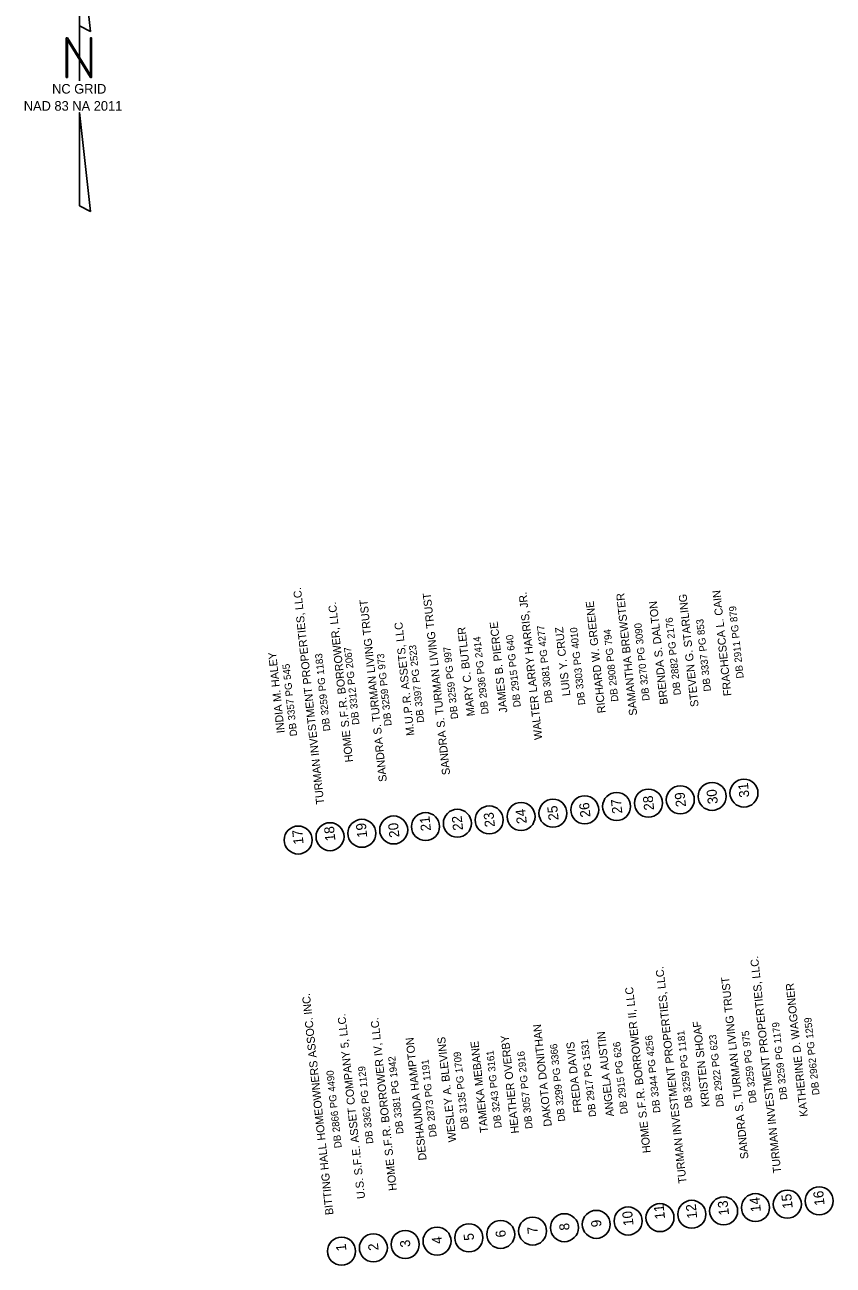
# Model space of a CAD drawing. Extents: x 1614427 to 1617186, y 896524 to 905462.
# Drawn here: x 1615655 to 1616160, y 902076 to 902852 of the extents above; entities that cross this region are included whole.
import ezdxf

# ---------------------------------------------------------------- set-up
doc = ezdxf.new("R2010")
doc.units = 0
for name, color, linetype in [('CTL North Arrow NAD 83 NA 2011 CELL', 7, 'Continuous'), ('Exist Property Deed Book Text', 7, 'Continuous'), ('Exist Property Owner Number CELL', 7, 'Continuous'), ('Exist Property Owner Text', 7, 'Continuous')]:
    doc.layers.add(name, color=color, linetype=linetype)

msp = doc.modelspace()

# ---------------------------------------------------------------- linework, layer by layer
at = {"layer": 'CTL North Arrow NAD 83 NA 2011 CELL'}
msp.add_line((1615689.76, 902821.93), (1615689.76, 902821.93), dxfattribs=at)
for points in [[(1615689.61, 902909.22), (1615689.61, 902850.9), (1615696.48, 902847.46)], [(1615681.38, 902818.67), (1615682.07, 902818.67), (1615682.07, 902842), (1615696.48, 902818.67), (1615697.17, 902818.67), (1615697.17, 902843.36), (1615696.48, 902843.36), (1615696.48, 902820.03), (1615682.07, 902843.36), (1615681.38, 902843.36)], [(1615689.61, 902738.38), (1615696.48, 902734.97), (1615689.61, 902796.71)]]:
    msp.add_lwpolyline(points, close=True, dxfattribs=at)
msp.add_lwpolyline([(1615689.61, 902850.9), (1615689.61, 902816.6)], dxfattribs=at)
at = {"layer": 'Exist Property Owner Number CELL'}
for centre in [(1616064.92, 902367.33), (1616084.81, 902369.42), (1616104.7, 902371.52), (1615985.36, 902358.94), (1616005.25, 902361.04), (1616025.14, 902363.14), (1616045.03, 902365.23), (1615905.8, 902350.56), (1615925.69, 902352.65), (1615945.58, 902354.75), (1615965.47, 902356.85), (1615826.24, 902342.17), (1615846.13, 902344.27), (1615866.02, 902346.36), (1615885.91, 902348.46), (1616092, 902110.4), (1616111.89, 902112.5), (1616131.78, 902114.59), (1616151.67, 902116.69), (1616012.44, 902102.02), (1616032.33, 902104.11), (1616052.22, 902106.21), (1616072.11, 902108.31), (1615952.77, 902095.73), (1615972.66, 902097.82), (1615992.55, 902099.92), (1615873.21, 902087.34), (1615893.1, 902089.44), (1615912.99, 902091.53), (1615932.88, 902093.63), (1615853.32, 902085.25)]:
    msp.add_circle(centre, 8.75, dxfattribs=at)

# ---------------------------------------------------------------- texts
at = {"layer": 'CTL North Arrow NAD 83 NA 2011 CELL'}
for s, p in [('NC GRID', (1615672.53, 902808.6)), ('NAD 83 NA 2011', (1615654.84, 902797.92))]:
    msp.add_text(s, height=6, dxfattribs=at).set_placement(p)
at = {"layer": 'Exist Property Deed Book Text'}
for s, p in [('DB 2911 PG 879', (1616104.55, 902443.39)), ('DB 3081 PG 4277', (1615985.05, 902427.99)), ('DB 3303 PG 4010', (1616005.62, 902426.73)), ('DB 3270 PG 3090', (1616045.8, 902429.41)), ('DB 2882 PG 2176', (1616065.33, 902432.91)), ('DB 3337 PG 853', (1616084.1, 902435.27)), ('DB 2936 PG 2414', (1615945.23, 902421)), ('DB 2915 PG 640', (1615965.29, 902425.42)), ('DB 2908 PG 794', (1616026.29, 902428.87)), ('DB 3312 PG 2067', (1615864.53, 902414.37)), ('DB 3397 PG 2523', (1615905.01, 902415.72)), ('DB 3259 PG 997', (1615926.19, 902417.97)), ('DB 3357 PG 545', (1615825.65, 902407.26)), ('DB 3259 PG 1183', (1615846.36, 902410.41)), ('DB 3259 PG 973', (1615884.67, 902413.68)), ('DB 3259 PG 1179', (1616131.83, 902180.05)), ('DB 2962 PG 1259', (1616151.93, 902183.01)), ('DB 3344 PG 4256', (1616052.55, 902171.86)), ('DB 3259 PG 1181', (1616072.57, 902174.83)), ('DB 2922 PG 623', (1616092.11, 902175.6)), ('DB 3259 PG 975', (1616112.57, 902177.99)), ('DB 3299 PG 3366', (1615993.11, 902166.5)), ('DB 2917 PG 1531', (1616012.42, 902169.39)), ('DB 2915 PG 626', (1616032.13, 902171.11)), ('DB 3381 PG 1942', (1615892.07, 902158.72)), ('DB 2873 PG 1191', (1615912.78, 902156.75)), ('DB 3135 PG 1709', (1615932.85, 902161.57)), ('DB 3243 PG 3161', (1615953.37, 902162.37)), ('DB 3057 PG 2916', (1615972.69, 902161.91)), ('DB 2866 PG 4490', (1615853.46, 902149.88)), ('DB 3362 PG 1129', (1615873.25, 902152.56))]:
    msp.add_text(s, height=4.5, rotation=96.11804, dxfattribs=at).set_placement(p)
at = {"layer": 'Exist Property Owner Number CELL'}
for s, p in [('31', (1616108.11, 902369.06)), ('27', (1616028.74, 902358.92)), ('28', (1616048.63, 902361.01)), ('29', (1616068.52, 902363.11)), ('30', (1616088.43, 902364.96)), ('23', (1615949.18, 902350.53)), ('24', (1615969.07, 902352.63)), ('25', (1615988.96, 902354.73)), ('26', (1616008.86, 902356.67)), ('19', (1615869.43, 902343.91)), ('20', (1615889.53, 902344)), ('21', (1615909.21, 902348.1)), ('22', (1615929.29, 902348.44)), ('17', (1615829.65, 902339.72)), ('18', (1615849.54, 902341.81)), ('14', (1616115.3, 902110.04)), ('15', (1616135.19, 902112.14)), ('16', (1616155.09, 902114.09)), ('11', (1616055.44, 902105.51)), ('12', (1616075.52, 902105.85)), ('13', (1616095.41, 902107.95)), ('9', (1616015.74, 902100.59)), ('10', (1616035.76, 902101.41)), ('5', (1615936.18, 902092.2)), ('6', (1615956.08, 902094.15)), ('7', (1615975.96, 902096.4)), ('8', (1615995.85, 902098.49)), ('1', (1615856.43, 902085.58)), ('2', (1615876.51, 902085.91)), ('3', (1615896.4, 902088.01)), ('4', (1615916.29, 902090.11))]:
    msp.add_text(s, height=6.25, rotation=96.11804, dxfattribs=at).set_placement(p)
at = {"layer": 'Exist Property Owner Text'}
for s, p in [('TURMAN INVESTMENT PROPERTIES, LLC.', (1615842.51, 902364.69)), ('HOME S.F.R. BORROWER, LLC.', (1615860.56, 902391.05)), ('SANDRA S. TURMAN LIVING TRUST', (1615881.66, 902378.81)), ('SANDRA S. TURMAN LIVING TRUST', (1615921.18, 902383.08)), ('WALTER LARRY HARRIS, JR.', (1615978.76, 902405.08)), ('RICHARD W. GREENE', (1616018.31, 902421.69)), ('SAMANTHA BREWSTER', (1616038.03, 902420.25)), ('BRENDA S. DALTON', (1616057.2, 902427.09)), ('STEVEN G. STARLING', (1616076.38, 902425.62)), ('FRACHESCA L. CAIN', (1616096.98, 902432.41)), ('M.U.P.R. ASSETS, LLC', (1615898.87, 902407.63)), ('MARY C. BUTLER', (1615936.61, 902419.78)), ('JAMES B. PIERCE', (1615956.91, 902421.97)), ('LUIS Y. CRUZ', (1615996.26, 902432.41)), ('INDIA M. HALEY', (1615817.86, 902409.22)), ('TURMAN INVESTMENT PROPERTIES, LLC.', (1616127.98, 902134.33)), ('TURMAN INVESTMENT PROPERTIES, LLC.', (1616068.85, 902127.84)), ('HOME S.F.R. BORROWER II, LLC', (1616046.48, 902146.83)), ('SANDRA S. TURMAN LIVING TRUST', (1616107.56, 902143.09)), ('KATHERINE D. WAGONER', (1616144.63, 902169.55)), ('BITTING HALL HOMEOWNERS ASSOC. INC.', (1615848.34, 902108.13)), ('U.S. S.F.E. ASSET COMPANY 5, LLC.', (1615868.08, 902118.2)), ('HOME S.F.R. BORROWER IV, LLC.', (1615887.9, 902123.29)), ('KRISTEN SHOAF', (1616083.34, 902175.72)), ('HEATHER OVERBY', (1615964.24, 902159.08)), ('DAKOTA DONITHAN', (1615984.69, 902163.42)), ('ANGELA AUSTIN', (1616023.54, 902169.64)), ('DESHAUNDA HAMPTON', (1615906.48, 902142.22)), ('WESLEY A. BLEVINS', (1615925.06, 902153.66)), ('TAMEKA MEBANE', (1615944.92, 902159.56)), ('FREDA DAVIS', (1616003.39, 902172))]:
    msp.add_text(s, height=5, rotation=96.11804, dxfattribs=at).set_placement(p)

doc.saveas('drawing.dxf')
